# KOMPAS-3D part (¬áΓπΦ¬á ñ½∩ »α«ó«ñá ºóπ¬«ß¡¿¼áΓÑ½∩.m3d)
File: created 28.07.2016 20:11:28, last saved 28.07.2016 20:15:03.
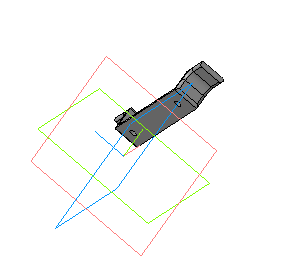
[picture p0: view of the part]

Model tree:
1. Эскиз:1
2. Операция выдавливания:1
     Расстояние 1 = 10
3. Скругление:1
     Радиус = 1
4. Скругление:2
     Радиус = 1
5. Скругление:3
     Радиус = 3
6. Скругление:4
     Радиус = 3
7. Эскиз:2
8. Вырезать элемент выдавливания:1
     Расстояние 1 = 3; Угол 1 = 30
9. Скругление:5
     Радиус = 1
10. Скругление:6
     Радиус = 1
